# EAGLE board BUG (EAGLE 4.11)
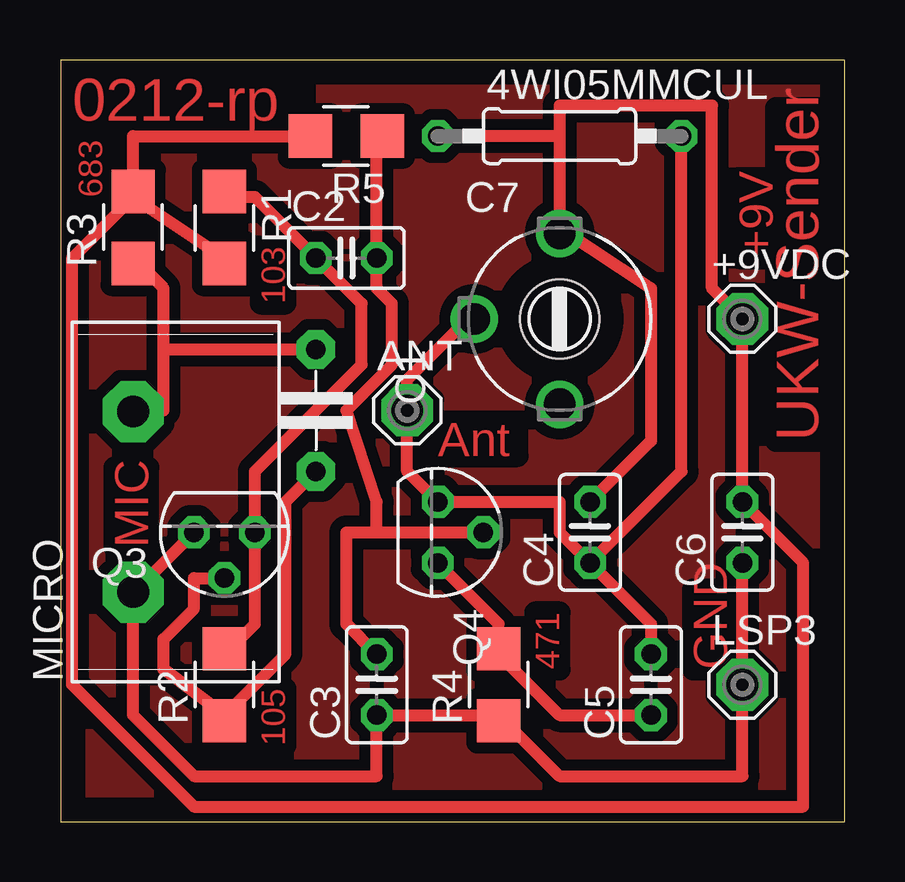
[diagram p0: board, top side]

Size 32.69 x 31.74 mm. Coordinates in mm from the lower left corner, seen from the top.
Outline: 0,0 32.69,0 32.69,31.74 0,31.74 0,0
Copper layers 1: Top 0.035mm
Design rules "default": minimum track width 20mil, minimum drill 24mil, track to track 18mil, track to pad 18mil, pad to pad 18mil, via to via 18mil, smd to smd 18mil, copper to edge 40mil, drill to drill 8mil, minimum pad ring 10mil, minimum via ring 8mil, stop-mask expansion 4mil, vias tented up to drill 0mil, thermal gap 10mil

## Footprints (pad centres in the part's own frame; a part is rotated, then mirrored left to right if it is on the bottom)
0207/10 = drill 0.813 octagon: 1 -5.08,0; 2 5.08,0
SE13 = drill 1.321 pad 2.159 octagon: MP 0,0
C-5 = drill 0.813 pad 1.6 octagon: 1 -2.54,0; 2 2.54,0
C025-025X050 = drill 0.813 octagon: 1 -1.27,0; 2 1.27,0
CTRIM808-1 = drill 1.321 round: 1 -3.556,0; 2 0,-3.556; 3 3.556,0 | hole 3.302: 0,0
B/C11S = drill 1.321 pad 2.54 octagon: 1 -3.759,0; 2 3.759,0
TO92 = drill 0.813 octagon: 1 1.27,0; 2 0,1.905; 3 -1.27,0
R1210W = smd 1.8 x 1.8: 1 -1.499,0; 2 1.499,0

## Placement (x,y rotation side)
4WI05MMCUL  Durchmess 3mm  [0207/10]  20.79,28.57 0 top
+9VDC  SE13  [SE13]  28.41,20.95 0 top
ANT  SE13  [SE13]  14.44,17.14 0 top
C1  22n  [C-5]  10.63,17.14 270 top
C2  100n  [C025-025X050]  11.9,23.49 0 top
C3  1n  [C025-025X050]  13.17,5.71 90 top
C4  39p  [C025-025X050]  22.06,12.06 90 top
C5  10p  [C025-025X050]  24.6,5.71 90 top
C6  22n  [C025-025X050]  28.41,12.06 90 top
C7  [CTRIM808-1]  20.79,20.95 270 top
LSP3  Masse  [SE13]  28.41,5.71 0 top
MICRO  ..  [B/C11S]  3.01,13.33 90 top
Q3  BC547B  [TO92]  6.82,12.06 180 top
Q4  BC547B  [TO92]  15.71,12.06 270 top
R1  10K  [R1210W]  6.82,24.76 270 top
R2  1M  [R1210W]  6.82,5.71 90 top
R3  68k  [R1210W]  3.01,24.76 90 top
R4  470  [R1210W]  18.25,5.71 90 top
R5  47K  [R1210W]  11.9,28.57 180 top

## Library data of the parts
4WI05MMCUL C2-C7 R1-R5 = rcl
+9VDC ANT LSP3 = solpad
C1 = discrete
MICRO = buzzer
Q3 Q4 = transistor-npn

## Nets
MM: C3.1 C6.1 LSP3.MP MICRO.1 R4.1
N$2: C1.1 MICRO.2 R3.1
N$5: C1.2 Q3.2 R2.1
N$6: C2.1 Q3.3 R1.1 R2.2
N$8: 4WI05MMCUL.1 +9VDC.MP C4.2 C6.2 C7.1 R1.2 R3.2 R5.2
N$10: C5.1 Q4.1 R4.2
N$11: C3.2 Q4.2
N$13: 4WI05MMCUL.2 ANT.MP C4.1 C5.2 C7.2 Q4.3
S$2: Q3.1
S$3: C2.2 R5.1

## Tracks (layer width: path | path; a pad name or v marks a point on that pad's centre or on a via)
MM
  Top 0.508: C6.1 | LSP3.MP C6.1 | LSP3.MP | LSP3.MP 28.41,1.9 20.79,1.9 18.25,4.44 | 18.25,4.44 R4.1 | MICRO.1 3.01,9.52 3.01,4.44 5.55,1.9 13.17,1.9 C3.1 | C3.1 18.25,4.44 | C3.1
N$2
  Top 0.508: 4.28,19.68 C1.1 | 4.28,19.68 4.28,17.14 MICRO.2 | C1.1 | 4.28,19.68 4.28,22.22 3.01,23.49 R3.1
N$5
  Top 0.508: 6.82,4.44 4.28,6.34 4.28,7.61 5.55,8.88 5.55,10.16 Q3.2 | 6.82,4.44 9.36,6.98 9.36,13.33 C1.2 | R2.1 6.82,4.44
N$6
  Top 0.508: Q3.3 8.09,8.25 6.82,6.98 R2.2 | C2.1 8.09,26.03 6.82,26.03 R1.1 | Q3.3 8.09,14.6 12.54,19.04 12.54,21.59 C2.1 | Q3.3 | C2.1
N$8
  Top 0.508: 3.01,26.03 6.82,23.49 R1.2 | 3.01,26.03 3.01,28.57 10.63,28.57 R5.2 | C6.2 +9VDC.MP | 20.79,28.57 4WI05MMCUL.1 | 20.79,28.57 20.79,24.76 | 4WI05MMCUL.1 | 20.79,24.76 C7.1 | C4.2 24.6,15.87 24.6,22.22 20.79,24.76 | C4.2 | +9VDC.MP 27.14,22.22 27.14,29.84 20.79,29.84 20.79,28.57 | +9VDC.MP | 3.01,26.03 0.47,23.49 0.47,5.71 5.55,0.63 30.95,0.63 30.95,10.79 C6.2 | 3.01,26.03 R3.2 | C6.2
N$10
  Top 0.508: Q4.1 18.25,8.25 18.25,6.98 | Q4.1 | C5.1 20.79,4.44 18.25,6.98 | C5.1 | 18.25,6.98 R4.2
N$11
  Top 0.508: Q4.2 16.98,12.06 11.9,12.06 | 11.9,12.06 12.54,12.06 | 11.9,12.06 11.9,8.25 C3.2 | C3.2
N$13
  Top 0.508: Q4.3 14.44,14.6 ANT.MP | ANT.MP 14.44,18.41 16.98,20.95 C7.2 | ANT.MP | C4.1 24.6,8.25 C5.2 | C5.2 | 4WI05MMCUL.2 25.87,14.6 C4.1 | 4WI05MMCUL.2 | Q4.3 20.79,13.33 20.79,12.06 C4.1 | Q4.3 | C4.1
S$1
  pour Top: -0.8,32.38 33.49,32.38 33.49,-0.64 -0.8,-0.64
S$2
  Top 0.508: 3.01,9.52 Q3.1
S$3
  Top 0.508: R5.1 13.17,28.57 C2.2 | C2.2 | C2.2 | C2.2 13.17,22.22 13.8,21.59 13.8,19.04 11.9,17.14 13.17,13.33 13.17,12.06

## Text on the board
Top: 0212-rp | 683 | +9V | 103 | UKW-Sender | Ant | MIC | 471 | GND | 105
